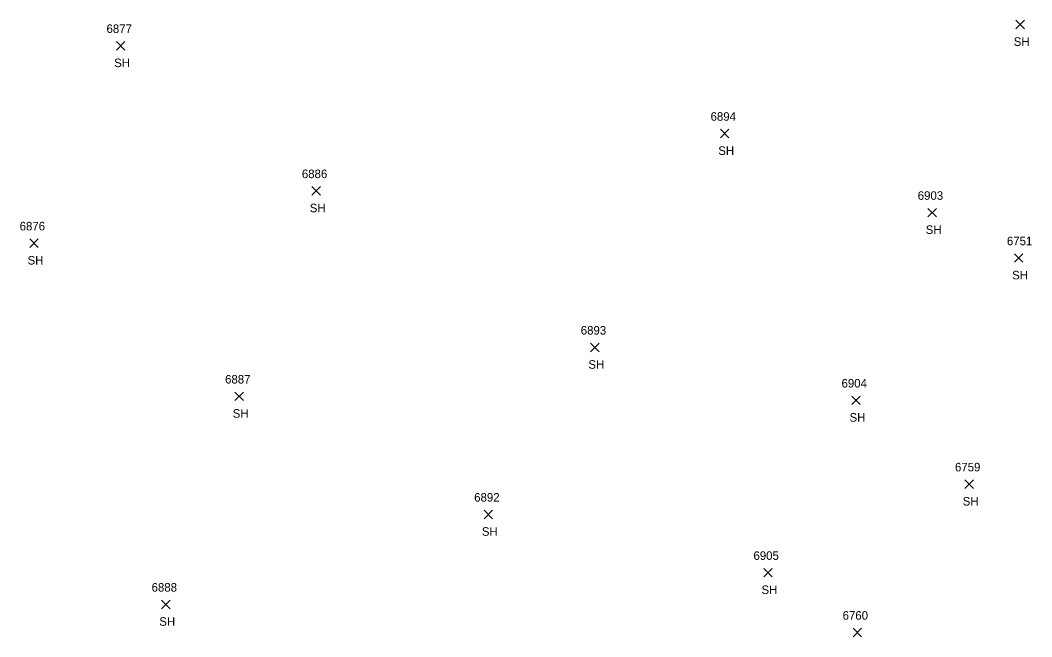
# Model space of a CAD drawing. Extents: x 1678863 to 1683592, y 407783 to 418211.
# Drawn here: x 1680584.1 to 1680821, y 409202.5 to 409346.9 of the extents above; entities that cross this region are included whole.
import ezdxf

# ---------------------------------------------------------------- set-up
doc = ezdxf.new("R2010")
doc.units = 0
for name, color, linetype in [('L_A', 7, 'Continuous'), ('L_I', 7, 'Continuous'), ('L_TIC', 7, 'Continuous')]:
    doc.layers.add(name, color=color, linetype=linetype)

msp = doc.modelspace()

# ---------------------------------------------------------------- linework, layer by layer
at = {"layer": 'L_TIC'}
for points in [[(1680817.32, 409344.91), (1680819.32, 409346.91)], [(1680819.32, 409344.91), (1680817.32, 409346.91)], [(1680606.59, 409339.93), (1680608.59, 409341.93)], [(1680608.59, 409339.93), (1680606.59, 409341.93)], [(1680748.1, 409319.37), (1680750.1, 409321.37)], [(1680750.1, 409319.37), (1680748.1, 409321.37)], [(1680652.41, 409305.93), (1680654.41, 409307.93)], [(1680654.41, 409305.93), (1680652.41, 409307.93)], [(1680796.7, 409300.85), (1680798.7, 409302.85)], [(1680798.7, 409300.85), (1680796.7, 409302.85)], [(1680586.3, 409293.69), (1680588.3, 409295.69)], [(1680588.3, 409293.69), (1680586.3, 409295.69)], [(1680816.95, 409290.21), (1680818.95, 409292.21)], [(1680818.95, 409290.21), (1680816.95, 409292.21)], [(1680717.69, 409269.28), (1680719.69, 409271.28)], [(1680719.69, 409269.28), (1680717.69, 409271.28)], [(1680634.36, 409257.81), (1680636.36, 409259.81)], [(1680636.36, 409257.81), (1680634.36, 409259.81)], [(1680778.86, 409256.88), (1680780.86, 409258.88)], [(1680780.86, 409256.88), (1680778.86, 409258.88)], [(1680805.37, 409237.24), (1680807.37, 409239.24)], [(1680807.37, 409237.24), (1680805.37, 409239.24)], [(1680692.73, 409230.16), (1680694.73, 409232.16)], [(1680694.73, 409230.16), (1680692.73, 409232.16)], [(1680758.23, 409216.51), (1680760.23, 409218.51)], [(1680760.23, 409216.51), (1680758.23, 409218.51)], [(1680617.16, 409209.08), (1680619.16, 409211.08)], [(1680619.16, 409209.08), (1680617.16, 409211.08)], [(1680779.17, 409202.5), (1680781.17, 409204.5)], [(1680781.17, 409202.5), (1680779.17, 409204.5)]]:
    msp.add_lwpolyline(points, dxfattribs=at)

# ---------------------------------------------------------------- texts
at = {"layer": 'L_A'}
for p in [(1680816.81, 409340.91), (1680606.08, 409335.93), (1680747.59, 409315.37), (1680651.9, 409301.93), (1680796.19, 409296.85), (1680585.79, 409289.69), (1680816.44, 409286.21), (1680717.17, 409265.28), (1680633.85, 409253.81), (1680778.35, 409252.88), (1680804.86, 409233.24), (1680692.21, 409226.16), (1680757.72, 409212.51), (1680616.65, 409205.08)]:
    msp.add_text('SH', height=2, dxfattribs=at).set_placement(p)
at = {"layer": 'L_I'}
for s, p in [('6877', (1680604.29, 409343.93)), ('6894', (1680745.79, 409323.37)), ('6886', (1680650.05, 409309.93)), ('6903', (1680794.32, 409304.85)), ('6876', (1680583.94, 409297.69)), ('6751', (1680815.21, 409294.21)), ('6893', (1680715.38, 409273.28)), ('6887', (1680632.06, 409261.81)), ('6904', (1680776.47, 409260.88)), ('6759', (1680803.05, 409241.24)), ('6892', (1680690.42, 409234.16)), ('6905', (1680755.84, 409220.51)), ('6888', (1680614.85, 409213.08)), ('6760', (1680776.73, 409206.5))]:
    msp.add_text(s, height=2, dxfattribs=at).set_placement(p)

doc.saveas('drawing.dxf')
